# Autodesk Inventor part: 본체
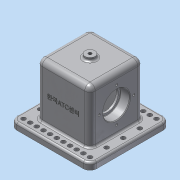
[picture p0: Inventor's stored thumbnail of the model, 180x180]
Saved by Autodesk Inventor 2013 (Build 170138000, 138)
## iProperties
Created: 2018-11
Part Number: 본체
Material: 알루미늄 6061
Document SubType Name: Modeling
Designer: dgall
Density: 2.71 g/cm^3
Mass: 1020.76 g
Surface Area: 777.082 cm^2
Volume: 376.663 cm^3
Author: dgall
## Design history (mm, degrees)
sketch "스케치1"
  geometry: L1 (-40, 40)-(40, 40); L2 (40, 40)-(40, -40); L3 (40, -40)-(-40, -40); L4 (-40, -40)-(-40, 40); 3 further points
  constraints: 8 end point, 2 midpoint, 2 parallel, 2 perpendicular, 1 horizontal, 1 horizontal alignment, 1 vertical alignment
  dimensions: "d0" = 80 distance of L1.start L1.end
extrude "돌출1" new body sketch "스케치1" distance "d2" = 90; taper "d3" = 0 deg
sketch "스케치2"
  geometry: L1 (-60, 60)-(60, 60); L2 (60, 60)-(60, -60); L3 (60, -60)-(-60, -60); L4 (-60, -60)-(-60, 60); L5 (-23, 30)-(23, 30); L6 (23, 30)-(23, -30); L7 (23, -30)-(-23, -30); L8 (-23, -30)-(-23, 30); 5 further points
  constraints: 16 end point, 4 midpoint, 4 parallel, 3 perpendicular, 2 horizontal, 2 horizontal alignment, 2 vertical alignment
  dimensions: "d4" = 120 distance of L1.start L1.end; "d6" = 60 distance of L5.end L6.end; "d7" = 46 distance of L5.start L5.end
extrude "돌출2" join sketch "스케치2" distance "d8" = 10; taper "d9" = 0 deg
extrude "돌출3" cut sketch "스케치2" distance "d10" = 80; taper "d11" = 0 deg
sketch "스케치3"
  geometry: L1 (-90, 100)-(-90, -20) reference; C1 r 20 at (-42, 40); 2 further points
  constraints: 1 centre point, 1 horizontal alignment, 1 midpoint
  dimensions: "d12" = 40 diameter of C1; "d13" = 48 distance from line of L1 C1.centre
extrude "돌출4" cut sketch "스케치3" distance "d14" = 14; taper "d15" = 0 deg
hole "구멍1" diameter "d18" = 33; stored, may be unused: countersink angle "d22" = 90 deg, drill point angle "d24" = 118 deg; dims "d16" = 10, "d17" = 10, "d19" = 6, "d20" = 4, "d21" = 2, "d23" = 8
fillet "모깎기1" dims "d25" = 10
fillet "모깎기2" dims "d26" = 8
fillet "모깎기3" dims "d27" = 3
node "작업 평면1"
sketch "스케치4"
  geometry: C1 r 7.5 at (0, 0); 1 further point
  constraints: 1 centre point, 1 coincident
  dimensions: "d29" = 15 diameter of C1
extrude "돌출5" join sketch "스케치4" stored distance "d30" = 14; taper "d31" = 0 deg
hole "구멍2" diameter "d34" = 4.917; stored, may be unused: countersink angle "d38" = 90 deg, drill point angle "d40" = 118 deg; dims "d32" = 10, "d33" = 10, "d35" = 6, "d36" = 4, "d37" = 2, "d39" = 8
fillet "모깎기4" dims "d41" = 3
sketch "스케치5"
  geometry: C1 r 3.3 at (-50, 50); C2 r 3.3 at (-50, 25); C3 r 3.3 at (-50, 0); C4 r 3.3 at (-50, -25); C5 r 3.3 at (-50, -50); C6 r 3.3 at (-40, 50); C7 r 3.3 at (-30, 50); C8 r 3.3 at (-20, 50); C9 r 3.3 at (-10, 50); C10 r 3.3 at (0, 50); C11 r 3.3 at (10, 50); C12 r 3.3 at (20, 50); C13 r 3.3 at (30, 50); C14 r 3.3 at (40, 50); C15 r 3.3 at (50, 50); A1 r 10 centre (-50, 50) between (-50, 60) and (-60, 50) reference; A2 r 10 centre (-50, -50) between (-60, -50) and (-50, -60) reference; 1 further point
  constraints: 15 centre point, 10 equal radius, 10 horizontal alignment, 4 vertical alignment, 2 coincident
  dimensions: "d42" = 6.6 diameter of C1; "d43" = 6.6 diameter of C2; "d44" = 6.6 diameter of C3; "d45" = 6.6 diameter of C4; "d46" = 6.6 diameter of C5; "d47" = 25 distance of C1.centre C2.centre; "d48" = 25 distance of C2.centre C3.centre; "d49" = 25 distance of C5.centre C4.centre; "d50" = 10 distance of C6.centre C1.centre; "d51" = 10 distance of C7.centre C6.centre; "d52" = 10 distance of C8.centre C7.centre; "d53" = 10 distance of C9.centre C8.centre; "d54" = 10 distance of C10.centre C9.centre; "d55" = 10 distance of C11.centre C10.centre; "d56" = 10 distance of C12.centre C11.centre; "d57" = 10 distance of C13.centre C12.centre; "d58" = 10 distance of C14.centre C13.centre; "d59" = 10 distance of C15.centre C14.centre
extrude "돌출6" cut sketch "스케치5" stored distance "d60" = 14; taper "d61" = 0 deg
extrude "돌출7" cut sketch "스케치5" stored distance "d62" = 14; taper "d63" = 0 deg
fillet "모깎기5" dims "d64" = 3
chamfer "모따기1" distance "d65" = 1; stored, may be unused: second distance "d66" = 2, angle "d67" = 45 deg
fillet "모깎기6" dims "d68" = 0.6
sketch "스케치6"
  geometry: L1 (-82, 82)-(-82, -18) reference; C1 r 16.5 at (-34, 32) reference; 3 further points
  constraints: 1 horizontal alignment, 1 midpoint
  dimensions: "d69" = 26 distance of C1.centre point (-8, 32)
hole "구멍3" sketch "스케치6" at (-8, 32) diameter "d70" = 3.242; stored, may be unused: countersink angle "d74" = 90 deg, drill point angle "d76" = 118 deg; dims "d71" = 8, "d72" = 4, "d73" = 2, "d75" = 10
sketch "스케치7"
  geometry: L1 (-18, -82)-(82, -82) reference; 3 further points
  constraints: 1 midpoint, 1 vertical alignment, 1 other
  dimensions: "d80" = 48 distance from line of L1 point (32, -34)
feature "엠보싱1" sketch "스케치7" dims "d0" = 80, "d10" = 80, "d81" = 0.5, "d82" = 0
node "솔리드1"
mirror "대칭1"
mirror "대칭2"
mirror "대칭3"
pattern_circular "원형 패턴1" dims angle "d78" = 360 deg
mirror "대칭4"
other parameters: "d28" = 5
